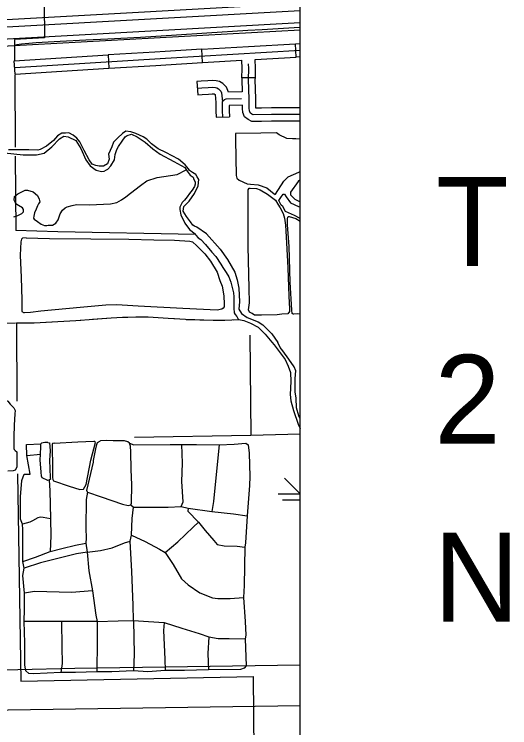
# Model space of a CAD drawing. Extents: x 1127717 to 1741049, y 2026793 to 2244711.
# Drawn here: x 1346418 to 1351991, y 2083351 to 2091369 of the extents above; entities that cross this region are included whole.
import ezdxf

# ---------------------------------------------------------------- set-up
doc = ezdxf.new("R2010")
doc.units = 0
for name, color, linetype in [('1', 7, 'Continuous'), ('15', 7, 'Continuous'), ('19', 7, 'Continuous'), ('27', 7, 'Continuous'), ('31', 7, 'Continuous'), ('34', 7, 'Continuous'), ('35', 7, 'Continuous'), ('40', 7, 'Continuous'), ('43', 7, 'Continuous'), ('44', 7, 'Continuous'), ('5', 7, 'Continuous'), ('6', 7, 'Continuous'), ('R_Draft', 7, 'Continuous')]:
    doc.layers.add(name, color=color, linetype=linetype)

msp = doc.modelspace()

# ---------------------------------------------------------------- linework, layer by layer
at = {"layer": '1'}
msp.add_lwpolyline([(1349634.2, 2111942.3), (1278362.7, 2111942.3), (1278362.7, 2066677.1), (1349634.2, 2066677.1)], close=True, dxfattribs=at)
at = {"layer": '15'}
msp.add_lwpolyline([(1342805.9, 2083498.8), (1349634.2, 2083599.2)], dxfattribs=at)
at = {"layer": '19'}
for points in [[(1346037.2, 2091291.5), (1346331.6, 2091309.2), (1349634.2, 2091492.7)], [(1349634.2, 2091407.5), (1346336.5, 2091224.3), (1346026.2, 2091205.7)], [(1346015.3, 2091074.8), (1346344, 2091094.5), (1349634.2, 2091277.3)], [(1349634.2, 2091192.2), (1346348.9, 2091009.7), (1345976, 2090987.3)]]:
    msp.add_lwpolyline(points, dxfattribs=at)
at = {"layer": '27'}
for p, q in [((1349590, 2090887.6), (1349581.3, 2091037.3)), ((1347472.8, 2090912), (1347482, 2090762.3)), ((1348535.9, 2090825.8), (1348527.1, 2090975.6)), ((1348535.9, 2090825.8), (1348535.9, 2090825.8))]:
    msp.add_line(p, q, dxfattribs=at)
for points in [[(1348527.1, 2090975.6), (1349054.2, 2091006.4)], [(1349054.2, 2091006.4), (1349581.3, 2091037.3)], [(1349581.3, 2091037.3), (1349634.2, 2091040.4)], [(1346945.8, 2090879.7), (1347472.8, 2090912)], [(1347999.8, 2090944.4), (1347472.8, 2090912)], [(1348527.1, 2090975.6), (1348114.3, 2090951.4), (1347999.8, 2090944.4)], [(1346418.8, 2090847.4), (1346945.8, 2090879.7)], [(1348009, 2090794.7), (1348123.2, 2090801.7), (1348535.9, 2090825.8)], [(1348535.9, 2090825.8), (1348978.1, 2090851.7)], [(1349127.9, 2090860.5), (1349590, 2090887.6)], [(1349634.2, 2090890.1), (1349590, 2090887.6)], [(1346955, 2090730), (1347482, 2090762.3)], [(1347482, 2090762.3), (1348009, 2090794.7)], [(1346428, 2090697.7), (1346955, 2090730)]]:
    msp.add_lwpolyline(points, dxfattribs=at)
at = {"layer": '31'}
for p, q in [((1346428, 2090697.7), (1346418.8, 2090847.4)), ((1349129.6, 2090653.8), (1348979.6, 2090655.4)), ((1348471.5, 2090612.9), (1348484.4, 2090463.4)), ((1348688.3, 2090212.5), (1348838.2, 2090215.3))]:
    msp.add_line(p, q, dxfattribs=at)
for points in [[(1349634.2, 2091220.4), (1349626.5, 2091219.9), (1349205.7, 2091195.1), (1349044.1, 2091185.9), (1348582.7, 2091156.1), (1348244.7, 2091135.4), (1347839.6, 2091108.9), (1347471.8, 2091090.7), (1347224.1, 2091079.9), (1346933.4, 2091061.6), (1346664.2, 2091046.7), (1346501, 2091034.3), (1346446.3, 2091026), (1346421.8, 2091018.8)], [(1346423.4, 2090772.5), (1348118.8, 2090876.5), (1349634.2, 2090965.3)], [(1348979.6, 2090655.4), (1348980.8, 2090761), (1348978.1, 2090851.7)], [(1349129.6, 2090653.8), (1349130.8, 2090762.4), (1349127.9, 2090860.5)], [(1349634.2, 2090244.4), (1349312, 2090242.2), (1349106.8, 2090239.4), (1349089.8, 2090247.9), (1349071.4, 2090263.4), (1349062.9, 2090283.3), (1349060.1, 2090315.8), (1349058.7, 2090416.3), (1349054.4, 2090635.7), (1349055.8, 2090761.7), (1349054.3, 2090813.8)], [(1348979.6, 2090655.4), (1348979.4, 2090635.4), (1348982.1, 2090498.4)], [(1348826.3, 2090494.6), (1348807.1, 2090548.4), (1348762.7, 2090590.5), (1348727, 2090613.4), (1348690.8, 2090622.5), (1348642.9, 2090624.3), (1348595.8, 2090622.7), (1348520.4, 2090617.1), (1348471.5, 2090612.9)], [(1349197.6, 2090315.6), (1349135.4, 2090314.8), (1349135, 2090319.6), (1349133.6, 2090417.6), (1349129.4, 2090636), (1349129.6, 2090653.8)], [(1348478, 2090538.1), (1348526.4, 2090542.3), (1348599.8, 2090547.8), (1348642.8, 2090549.2), (1348680.2, 2090547.8), (1348696.8, 2090543.7), (1348716.2, 2090531.2), (1348742.5, 2090506.3), (1348749.4, 2090486.9), (1348759.1, 2090385.7)], [(1348982.1, 2090498.4), (1348826.3, 2090494.6)], [(1348484.4, 2090463.4), (1348532.5, 2090467.5), (1348603.9, 2090472.9), (1348642.6, 2090474.2), (1348667.6, 2090473.3), (1348669.7, 2090471.9), (1348676.1, 2090465.9), (1348684.4, 2090378.6)], [(1348763.3, 2090213.9), (1348761.9, 2090287.4), (1348759.1, 2090385.7), (1348763.3, 2090395.4), (1348781.3, 2090410.7), (1348800.7, 2090419), (1348975.3, 2090423.2)], [(1348684.4, 2090378.6), (1348684.6, 2090365.3), (1348686.9, 2090285.6), (1348688.3, 2090212.5)], [(1348984.6, 2090348.4), (1348835.3, 2090344.8), (1348836.9, 2090289.1), (1348838.2, 2090215.3)], [(1349199.6, 2090165.6), (1349089.6, 2090164.1), (1349048.2, 2090184.8), (1349009.4, 2090217.6), (1348989.2, 2090264.8), (1348985.1, 2090312), (1348984.6, 2090348.4)], [(1349634.2, 2090319.4), (1349311.2, 2090317.2), (1349197.6, 2090315.6)], [(1349634.2, 2090169.4), (1349312.7, 2090167.2), (1349199.6, 2090165.6)]]:
    msp.add_lwpolyline(points, dxfattribs=at)
at = {"layer": '34'}
for points in [[(1346265, 2087059.4), (1346345.1, 2087022.1), (1346371.7, 2086986.6), (1346411.6, 2086944.5), (1346427.1, 2086917.9), (1346424.9, 2086878), (1346418.3, 2086751.6), (1346411.6, 2086620.8), (1346413.8, 2086487.8), (1346418.3, 2086476.7), (1346429.3, 2086467.9), (1346448.7, 2086450)], [(1346448.7, 2086450), (1346448.7, 2086280.5), (1346428.6, 2086245.2), (1346405.1, 2086236.8), (1346344.7, 2086235.2)]]:
    msp.add_lwpolyline(points, dxfattribs=at)
at = {"layer": '35'}
for points in [[(1346307.5, 2089810.4), (1346516.6, 2089789.5), (1346668.2, 2089789.5), (1346754, 2089809.2), (1346840.1, 2089879), (1346928.4, 2089969.7), (1346974.9, 2089997.6), (1347026.1, 2089993), (1347109.8, 2089951.1), (1347167.9, 2089860.4), (1347223.7, 2089734.8), (1347272.5, 2089665), (1347337.6, 2089618.5), (1347398, 2089602.2), (1347430.6, 2089604.5), (1347456.2, 2089620.8), (1347470.1, 2089630.1), (1347502.7, 2089667.3), (1347544.5, 2089734.8), (1347551.5, 2089792.9), (1347572.4, 2089848.7), (1347591, 2089883.6), (1347632.9, 2089941.8), (1347665.4, 2089993), (1347688.7, 2090006.9), (1347737.5, 2090020.9), (1347800.3, 2089990.6), (1347890.9, 2089930.2), (1347977, 2089855.7), (1348058.3, 2089795.3), (1348214.1, 2089713.8), (1348335, 2089648.7), (1348362.9, 2089604.5), (1348397.8, 2089560.3), (1348430.3, 2089537.1), (1348437.3, 2089511.5), (1348451.2, 2089485.9), (1348451.2, 2089460.3), (1348444.3, 2089434.7), (1348418.7, 2089392.9), (1348390.8, 2089355.7), (1348362.9, 2089318.4), (1348332.7, 2089281.2), (1348307.1, 2089255.6), (1348279.2, 2089202.2), (1348279.2, 2089176.6), (1348290.8, 2089116.1), (1348337.3, 2089023.1), (1348390.9, 2088951.7), (1348452.7, 2088901.9), (1348456, 2088894.4)], [(1348579.1, 2088899.8), (1348472.2, 2088976.5), (1348446.6, 2088988.2), (1348425.7, 2088999.8), (1348400.1, 2089034.7), (1348355.9, 2089095.2), (1348316.4, 2089158), (1348325.7, 2089209.1), (1348386.1, 2089269.6), (1348446.6, 2089355.7), (1348486.1, 2089441.7), (1348493.1, 2089511.5), (1348476.8, 2089541.7), (1348460.5, 2089569.6), (1348423.3, 2089590.6), (1348390.8, 2089613.8), (1348376.8, 2089632.4), (1348342, 2089676.6), (1348265.2, 2089739.4), (1348123.4, 2089816.2), (1348037.4, 2089858), (1347963, 2089913.9), (1347909.5, 2089967.4), (1347867.7, 2089993), (1347786.3, 2090027.8), (1347730.5, 2090048.8), (1347674.7, 2090055.7), (1347637.5, 2090027.8), (1347584, 2089979), (1347532.9, 2089930.2), (1347514.3, 2089879), (1347479.4, 2089795.3), (1347486.4, 2089741.8), (1347465.5, 2089688.3), (1347421.3, 2089660.4), (1347374.8, 2089660.4), (1347335.3, 2089669.7), (1347295.7, 2089683.6), (1347260.9, 2089734.8), (1347205.1, 2089837.1), (1347153.9, 2089937.1), (1347123.7, 2089976.7), (1347079.5, 2090011.6), (1347033, 2090037.1), (1346995.8, 2090034.8), (1346954, 2090032.5), (1346902.8, 2090004.6), (1346861, 2089951.1), (1346779.6, 2089888.3), (1346709.9, 2089848.7), (1346684.3, 2089841.8), (1346582, 2089846.4), (1346351.8, 2089846.4)], [(1349634.2, 2089966.4), (1349585.6, 2089971.2), (1349546.7, 2089971.2), (1349484.7, 2089973.7), (1349396.2, 2090014.4), (1349365.8, 2090035.6), (1349193.2, 2090033.8), (1348907.5, 2090028.1), (1348906, 2089959.3), (1348913.9, 2089557.1), (1348921.9, 2089528.4), (1348948.8, 2089505.1), (1349036.6, 2089463.8), (1349075.4, 2089460.6), (1349161.3, 2089454), (1349259.3, 2089418.1), (1349342.4, 2089350.2), (1349352.2, 2089342.6), (1349356.1, 2089346.9), (1349449.8, 2089493.7), (1349499.2, 2089543.1), (1349619.3, 2089596.5), (1349634.2, 2089601.6)], [(1347068.5, 2089221.3), (1347119.2, 2089231.3), (1347264.6, 2089226), (1347500.6, 2089237.8), (1347572.2, 2089252.5), (1347625.5, 2089285.5), (1347671.4, 2089318.6), (1347726.5, 2089359), (1347836.7, 2089443.5), (1347910.1, 2089496.8), (1348024, 2089535.4), (1348250, 2089569), (1348353.2, 2089619.9)], [(1349634.2, 2089510.1), (1349611.4, 2089491.2), (1349523.7, 2089371.8), (1349526.5, 2089341.6), (1349574, 2089291.3), (1349634.2, 2089261.9)], [(1346411.6, 2089094.5), (1346459.3, 2089107.3), (1346501.6, 2089129.4), (1346523.6, 2089149.6), (1346521.8, 2089173.5), (1346510.8, 2089193.7), (1346466.7, 2089221.2), (1346446.5, 2089232.2), (1346431.8, 2089248.8), (1346418.9, 2089278.2), (1346422.6, 2089320.4), (1346459.3, 2089351.7), (1346540.1, 2089392.1), (1346565.9, 2089392.1), (1346630.1, 2089373.7), (1346679.7, 2089331.5), (1346698.1, 2089292.9), (1346707.3, 2089261.6), (1346692.6, 2089239.6), (1346679.7, 2089215.7), (1346663.2, 2089177.1), (1346644.8, 2089138.5), (1346639.3, 2089101.8), (1346635.6, 2089076.1), (1346641.1, 2089065.1), (1346677.9, 2089039.3), (1346720.1, 2089009.9), (1346758.7, 2088997.1), (1346786.2, 2088997.1), (1346800.9, 2088998.9), (1346832.1, 2089000.8), (1346848.7, 2089000.8), (1346887.2, 2089021), (1346912.9, 2089057.7), (1346935, 2089125.7), (1346962.5, 2089167.9), (1346990.1, 2089193.7), (1347012.1, 2089206.5), (1347068.5, 2089221.3)], [(1349493.5, 2088003.7), (1349429.3, 2087999.5), (1349373.4, 2087991.2), (1349199.4, 2087989.2), (1349120.7, 2087989.2), (1349093.8, 2088005.7), (1349064.8, 2088022.3), (1349054.5, 2088047.2), (1349062.8, 2088125.9), (1349058.6, 2088291.6), (1349050.3, 2088759.8), (1349050.3, 2088908.9), (1349050.3, 2089240.4), (1349050.3, 2089350.2), (1349050.3, 2089397.8), (1349060.7, 2089416.5), (1349073.1, 2089416.5), (1349141.4, 2089412.3), (1349184.9, 2089397.8), (1349265.7, 2089346), (1349354.7, 2089281.8), (1349381.7, 2089234.2), (1349410.6, 2089192.7), (1349443.8, 2089128.5), (1349456.2, 2089078.8), (1349468.6, 2088998), (1349479, 2088801.2), (1349493.5, 2088519.5), (1349505.9, 2088202.5), (1349514.2, 2088059.6)], [(1349634.2, 2089074), (1349571.1, 2089107.6), (1349469, 2089153.7), (1349438.8, 2089208.3), (1349418.7, 2089224.1), (1349395.7, 2089277.4), (1349417.3, 2089310.4), (1349441.7, 2089346.4), (1349456.1, 2089346.4), (1349477.7, 2089316.2), (1349525.1, 2089250), (1349614.2, 2089208.3), (1349634.2, 2089203.2)], [(1349539, 2088043), (1349522.5, 2088357.9), (1349510, 2088759.8), (1349491.4, 2089002.1), (1349491.4, 2089070.5), (1349493.5, 2089089.2), (1349497.6, 2089095.4), (1349510, 2089095.4), (1349584.6, 2089072.6), (1349634.2, 2089042.2)], [(1348456, 2088894.4), (1348458.7, 2088888.2), (1348487, 2088855.6), (1348515.4, 2088836.7), (1348569.5, 2088780.8), (1348640.7, 2088695.8), (1348683.6, 2088646), (1348742, 2088560.2), (1348764.3, 2088521.5), (1348802.9, 2088467.4), (1348831.3, 2088417.6), (1348854.4, 2088358.4), (1348866.5, 2088312), (1348884.5, 2088238.1), (1348886.2, 2088195.2), (1348886.2, 2088125.6), (1348888.8, 2088064.7), (1348893.1, 2088014.9), (1348902.5, 2087996.8), (1348920.5, 2087972.8), (1348933.4, 2087950.5), (1348943.1, 2087937.9)], [(1348579.1, 2088899.8), (1348735.4, 2088729.7), (1348816.2, 2088615), (1348899.6, 2088471.6), (1348925.6, 2088385.6), (1348943.9, 2088291.7), (1348951.7, 2088137.9), (1348943.9, 2088054.5), (1348975.5, 2088007.1), (1349038, 2087961.1), (1349160.9, 2087911.8), (1349215.8, 2087878.3), (1349316.5, 2087778.1), (1349384.3, 2087679.1)], [(1346552.2, 2088857.9), (1346512.7, 2088853.5), (1346499.6, 2088840.4), (1346493, 2088811.9), (1346486.5, 2088660.7), (1346495.2, 2088410.9), (1346501.8, 2088159), (1346501.8, 2088045), (1346504, 2088027.5), (1346530.3, 2088014.3)], [(1346552.2, 2088857.9), (1346812.8, 2088849.1), (1347279.3, 2088846.9), (1347708.6, 2088840.4), (1347988.9, 2088833.8), (1348221.1, 2088829.4), (1348394.1, 2088820.6)], [(1348394.1, 2088820.6), (1348422.6, 2088811.9), (1348470.8, 2088765.9), (1348560.6, 2088676), (1348626.3, 2088595), (1348700.7, 2088472.3), (1348731.4, 2088378.1), (1348755.5, 2088314.5), (1348775.2, 2088205), (1348779.6, 2088112.9), (1348779.6, 2088082.3), (1348768.6, 2088064.7), (1348751.1, 2088053.8), (1348698.5, 2088045)], [(1348698.5, 2088045), (1348315.3, 2088062.5), (1347811.5, 2088088.8), (1347572.8, 2088104.2), (1347447.9, 2088099.8), (1347158.8, 2088073.5), (1346716.4, 2088034.1), (1346600.3, 2088018.7), (1346530.3, 2088014.3)], [(1349514.2, 2088059.6), (1349514.2, 2088028.5), (1349493.5, 2088003.7)], [(1349634.2, 2088000.4), (1349609.4, 2088003.7), (1349563.9, 2087997.4), (1349553.5, 2087997.4), (1349545.2, 2088005.7), (1349539, 2088043)], [(1348943.1, 2087937.9), (1349001.2, 2087926.4), (1349074.2, 2087899.4), (1349160, 2087851.7), (1349239, 2087773.6), (1349314.9, 2087683.1), (1349342, 2087653.3)], [(1349342, 2087653.3), (1349466.4, 2087488.8), (1349500.3, 2087415.8), (1349526.3, 2087342.8), (1349528.9, 2087243.7), (1349521.1, 2087095.1), (1349528.9, 2087024.7), (1349557.6, 2086915.2), (1349609.7, 2086761.4), (1349634.2, 2086712.9)], [(1349634.2, 2086823.7), (1349620.2, 2086855.2), (1349594.1, 2086946.5), (1349588.9, 2087056), (1349575.9, 2087126.4), (1349578.5, 2087275), (1349583.7, 2087363.6), (1349568, 2087407.9), (1349508.1, 2087491.4), (1349437.7, 2087587.8), (1349409.1, 2087624.3), (1349384.3, 2087679.1)], [(1346865.5, 2086550.4), (1347133.6, 2086563.8), (1347314.3, 2086571.2)], [(1347157.3, 2086027.4), (1347197.3, 2086030.3), (1347226.9, 2086085.2), (1347278.8, 2086356.3), (1347332.1, 2086556.3), (1347314.3, 2086571.2)], [(1347243.2, 2085997.7), (1347234.3, 2086018.5), (1347247.7, 2086080.7), (1347311.3, 2086334.1), (1347311.3, 2086354.8), (1347335, 2086483.7), (1347345.4, 2086535.6), (1347355.8, 2086557.8), (1347389.8, 2086575.6)], [(1347243.2, 2085997.7), (1347395.8, 2085944.4), (1347634.2, 2085864.4), (1347700.9, 2085846.6), (1347727.5, 2085855.5), (1347737.9, 2085874.7), (1347739.4, 2086080.7), (1347732, 2086254.1), (1347730.5, 2086452.6), (1347726.1, 2086516.3), (1347714.2, 2086547.5), (1347696.4, 2086562.3), (1347657.9, 2086575.6), (1347632.8, 2086575.6), (1347530.6, 2086574.1), (1347450.6, 2086577.1), (1347389.8, 2086575.6)], [(1347714.2, 2086547.5), (1347764.5, 2086529.2), (1348173.4, 2086535.7), (1348304.2, 2086535.7), (1348467.8, 2086532.4), (1348722.9, 2086529.2), (1348893, 2086539), (1349023.8, 2086548.8), (1349050, 2086529.2), (1349059.8, 2086437.5), (1349069.6, 2086175.8), (1349063.1, 2086074.3), (1349036.9, 2085734), (1349017.3, 2085429.7), (1349010.7, 2085380.6), (1349004.2, 2084948.7), (1348997.6, 2084814.5), (1349014, 2084543), (1349023.8, 2084392.4), (1349014, 2084349.9), (1349027.1, 2084045.6), (1349004.2, 2084019.4), (1348961.7, 2084006.3), (1348601.9, 2084003), (1348333.6, 2083993.2), (1348114.5, 2083993.2), (1347921.5, 2083980.1), (1347761.2, 2083990), (1347515.9, 2083980.1), (1347345.8, 2083980.1), (1347107.1, 2083970.3), (1346943.5, 2083970.3), (1346636, 2083957.2), (1346580.4, 2083960.5), (1346547.7, 2083990), (1346537.9, 2084052.1), (1346537.9, 2084304.1), (1346531.4, 2084543), (1346534.6, 2084683.7), (1346534.6, 2084863.6), (1346515, 2085063.2), (1346528.1, 2085145), (1346515, 2085220.3), (1346515, 2085580.2), (1346511.8, 2085639.1), (1346488.9, 2085694.8), (1346488.9, 2085946.7), (1346505.2, 2086130), (1346531.4, 2086201.9), (1346596.8, 2086201.9), (1346560.8, 2086411.4), (1346557.5, 2086535.7), (1346715.9, 2086540)], [(1346732.2, 2086159.2), (1346723.3, 2086177), (1346721.8, 2086223), (1346714.4, 2086316.3), (1346710, 2086356.3), (1346714.4, 2086426), (1346715.9, 2086506), (1346715.9, 2086540), (1346723.3, 2086547.5)], [(1346797.4, 2086556.3), (1346760.4, 2086554.9), (1346723.3, 2086547.5)], [(1346797.4, 2086556.3), (1346815.2, 2086553.4), (1346819.6, 2086511.9), (1346821.1, 2086464.5), (1346813.7, 2086354.8), (1346818.1, 2086264.4), (1346822.6, 2086159.2), (1346824, 2086142.9), (1346812.2, 2086134.1), (1346797.4, 2086131.1)], [(1346865.5, 2086550.4), (1346849.2, 2086546), (1346843.3, 2086535.6), (1346846.3, 2086464.5), (1346849.2, 2086326.7), (1346847.7, 2086163.7), (1346850.7, 2086141.5), (1346861.1, 2086123.7)], [(1348294.4, 2085835.5), (1348317.3, 2085891.1), (1348304.2, 2086116.9), (1348310.8, 2086323), (1348304.2, 2086535.7)], [(1348722.9, 2086529.2), (1348696.7, 2086270.7), (1348660.7, 2085894.4), (1348641.1, 2085779.8)], [(1346560.8, 2086411.4), (1346714.4, 2086426)], [(1346797.4, 2086131.1), (1346732.2, 2086159.2)], [(1346812.2, 2086134.1), (1346819.2, 2086015.4), (1346825.8, 2085698), (1346829, 2085508.2), (1346822.5, 2085331.5)], [(1346861.1, 2086123.7), (1347034.4, 2086064.4), (1347157.3, 2086027.4)], [(1347243.2, 2085997.7), (1347228.1, 2085917.3), (1347224.8, 2085593.3), (1347228.1, 2085482.1), (1347224.8, 2085423.2), (1347237.9, 2085325), (1347257.5, 2085112.3), (1347296.8, 2084889.8), (1347336, 2084614.9), (1347349.1, 2084546.2), (1347352.4, 2084323.7), (1347345.8, 2083980.1)], [(1347727.5, 2085855.5), (1347758, 2085828.9), (1348150.5, 2085828.9), (1348294.4, 2085835.5), (1348372.9, 2085819.1), (1348641.1, 2085779.8), (1348883.2, 2085753.7), (1349036.9, 2085734)], [(1347758, 2084556), (1347754.7, 2084729.5), (1347741.6, 2085105.8), (1347722, 2085449.3), (1347738.3, 2085514.8), (1347744.9, 2085701.3), (1347758, 2085828.9)], [(1348372.9, 2085819.1), (1348369.6, 2085786.4), (1348490.7, 2085662), (1348565.9, 2085567.1), (1348664, 2085455.9), (1348700, 2085410.1), (1348778.5, 2085393.7), (1348925.7, 2085390.4), (1349010.7, 2085380.6)], [(1346825.8, 2085698), (1346744, 2085714.4), (1346711.3, 2085717.7), (1346681.8, 2085711.1), (1346623, 2085675.1), (1346593.5, 2085662), (1346511.8, 2085639.1)], [(1348114.5, 2085321.7), (1348258.4, 2085439.5), (1348431.8, 2085603.1), (1348490.7, 2085662)], [(1347237.9, 2085325), (1347388.4, 2085341.4), (1347519.2, 2085374.1), (1347656.6, 2085429.7), (1347722, 2085449.3)], [(1347738.3, 2085514.8), (1347888.8, 2085442.8), (1348052.3, 2085357.7), (1348114.5, 2085321.7), (1348206.1, 2085184.3), (1348297.7, 2085024), (1348372.9, 2084958.5), (1348503.7, 2084866.9), (1348647.7, 2084811.3), (1348706.5, 2084801.5), (1348847.2, 2084804.7), (1348997.6, 2084814.5)], [(1346515, 2085220.3), (1346655.7, 2085269.4), (1346822.5, 2085331.5), (1346953.3, 2085364.3), (1347107.1, 2085403.5), (1347224.8, 2085423.2)], [(1347237.9, 2085325), (1347120.1, 2085305.4), (1346714.5, 2085203.9), (1346528.1, 2085145)], [(1347296.8, 2084889.8), (1347061.3, 2084870.2), (1346645.9, 2084880), (1346534.6, 2084863.6)], [(1347349.1, 2084546.2), (1346950.1, 2084543), (1346662.2, 2084543), (1346531.4, 2084543)], [(1346950.1, 2084543), (1346953.3, 2084261.5), (1346956.6, 2084071.8), (1346943.5, 2083970.3)], [(1347349.1, 2084546.2), (1347587.9, 2084552.8), (1347758, 2084556), (1347928.1, 2084546.2), (1348104.7, 2084533.1), (1348304.2, 2084471), (1348497.2, 2084408.8), (1348605.1, 2084372.8), (1348709.8, 2084353.2), (1348834.1, 2084353.2), (1349014, 2084349.9)], [(1347758, 2084556), (1347767.8, 2084176.5), (1347761.2, 2083990)], [(1348104.7, 2084533.1), (1348098.1, 2084444.8), (1348111.2, 2084120.8), (1348114.5, 2083993.2)], [(1348605.1, 2084372.8), (1348595.3, 2084186.3), (1348601.9, 2084003)]]:
    msp.add_lwpolyline(points, dxfattribs=at)
at = {"layer": '40'}
msp.add_lwpolyline([(1342255.1, 2083927.7), (1344530.6, 2083960.2), (1347101.1, 2084021.6), (1349634.2, 2084056.3)], dxfattribs=at)
at = {"layer": '43'}
for points in [[(1346442.2, 2087901), (1346642.6, 2087902.6), (1347108.9, 2087927.5), (1347507.1, 2087957.4), (1347636.6, 2087964.1), (1347784.3, 2087967.4), (1347923.7, 2087969), (1348151, 2087952.4), (1348345.1, 2087940.8), (1348655.4, 2087932.5), (1348788.2, 2087932.5), (1348943.1, 2087937.9)], [(1346772, 2087909.6), (1347108.9, 2087927.5), (1347167.3, 2087931.9)], [(1347298.9, 2087941.8), (1347507.1, 2087957.4), (1347636.6, 2087964.1), (1347694.2, 2087965.4)], [(1347826.2, 2087967.9), (1347923.7, 2087969), (1348151, 2087952.4), (1348221.4, 2087948.2)], [(1348353.2, 2087940.6), (1348655.4, 2087932.5), (1348749.1, 2087932.5)], [(1348881, 2087935.7), (1348943.1, 2087937.9)], [(1344525, 2087478.1), (1344509.4, 2087734.3), (1344561.6, 2087786.6), (1344692.3, 2087812.8), (1345445, 2087838.9), (1345894.6, 2087865.1), (1346297.1, 2087896.4), (1346431.4, 2087900.6)], [(1346140.4, 2087884.2), (1346297.1, 2087896.4), (1346431.4, 2087900.6)], [(1346442.2, 2087901), (1346640.1, 2087902.6)]]:
    msp.add_lwpolyline(points, dxfattribs=at)
at = {"layer": '44'}
for p, q in [((1349634.2, 2085980.3), (1349458.1, 2086156.5)), ((1349384.9, 2085979.7), (1349634.2, 2085979.7)), ((1349434.9, 2085911.6), (1349634.2, 2085911.6))]:
    msp.add_line(p, q, dxfattribs=at)
at = {"layer": '5'}
for points in [[(1349069, 2087763), (1349079.7, 2086636.1)], [(1349634.2, 2086650), (1349079.7, 2086636.1)], [(1349079.7, 2086636.1), (1347770.5, 2086612.5)]]:
    msp.add_lwpolyline(points, dxfattribs=at)
at = {"layer": '6'}
for points in [[(1346751.3, 2091877.4), (1346758.2, 2091102.7)], [(1346758.2, 2091102.7), (1346421.3, 2091084.3), (1346422.8, 2090853.5)], [(1346423.9, 2090688.3), (1346429.2, 2089877.1)], [(1346429.9, 2089774.4), (1346435.4, 2088938.4)], [(1348456, 2088894.4), (1346909.9, 2088922.8), (1346435.4, 2088938.4)], [(1346442.2, 2087901), (1346447.9, 2087022.8)], [(1346456.5, 2086203.4), (1346490.8, 2083873.6)], [(1346490.8, 2083873.6), (1349107.3, 2083927.8)], [(1349133.1, 2081389.3), (1349107.3, 2083927.8)]]:
    msp.add_lwpolyline(points, dxfattribs=at)

# ---------------------------------------------------------------- texts
at = {"layer": 'R_Draft'}
for s, p in [('T', (1351162.3, 2088541.7)), ('2', (1351143.6, 2086541.7)), ('N', (1351134.2, 2084541.7))]:
    msp.add_text(s, height=1000, dxfattribs=at).set_placement(p)

doc.saveas('drawing.dxf')
